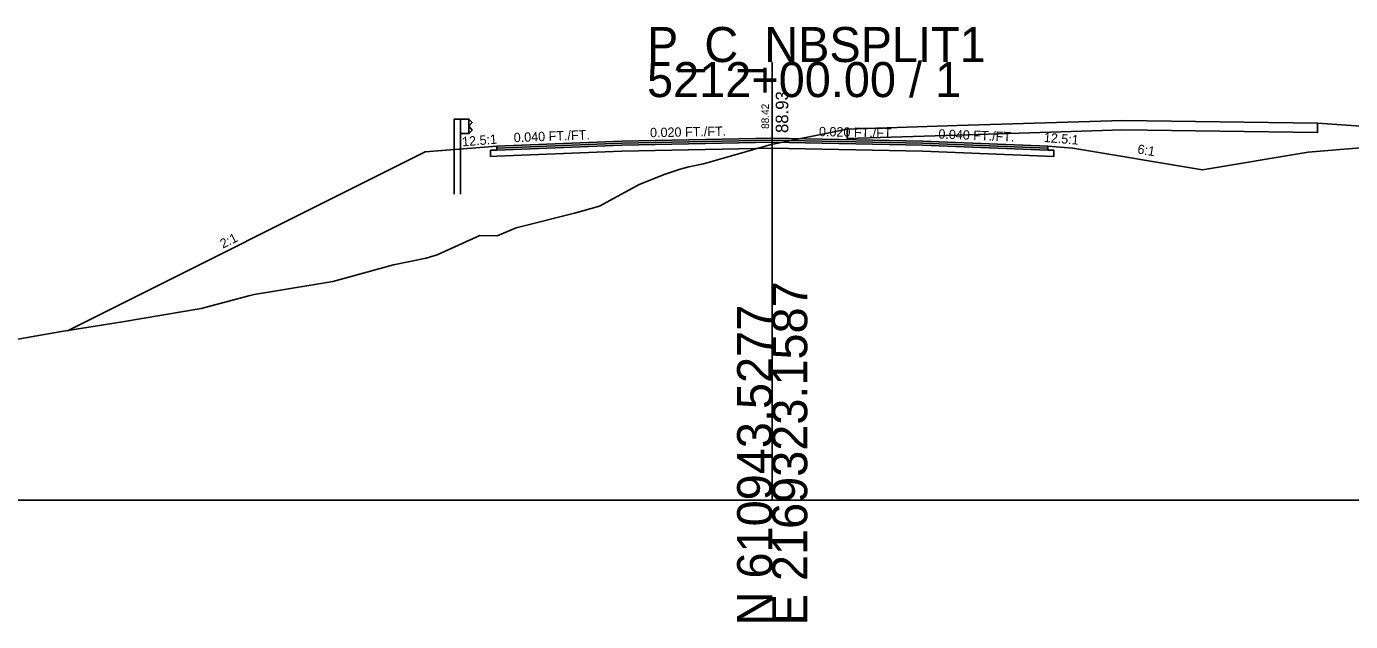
# Model space of a CAD drawing. Extents: x -26 to 1303, y -3010 to 12038.
# Drawn here: x 1090.4 to 1196.2, y 6990.3 to 7037.8 of the extents above; entities that cross this region are included whole.
import ezdxf

# ---------------------------------------------------------------- set-up
doc = ezdxf.new("R2010")
doc.units = 0
for name, color, linetype in [('RD_GPK_XS_Cell', 7, 'Continuous'), ('RD_PD_Final_TrvlWay', 7, 'Continuous'), ('RD_XS_Base', 7, 'Continuous'), ('RD_XS_ExGround', 7, 'Continuous'), ('RD_XS_ExPaveRet', 7, 'Continuous'), ('RD_XS_GR', 7, 'Continuous'), ('RD_XS_Greenside', 7, 'Continuous'), ('RD_XS_Pave', 7, 'Continuous'), ('RD_XS_PaveOvlay_CP', 7, 'Continuous'), ('RD_XS_TieSlope', 7, 'Continuous'), ('RD_XS_TX_Elev_EX', 7, 'Continuous'), ('RD_XS_TX_Elev_PR', 7, 'Continuous'), ('RD_XS_TX_ShdSlope', 7, 'Continuous'), ('RD_XS_TX_Slope', 7, 'Continuous')]:
    doc.layers.add(name, color=color, linetype=linetype)

msp = doc.modelspace()

# ---------------------------------------------------------------- linework, layer by layer
at = {"layer": 'RD_GPK_XS_Cell'}
for p, q in [((1150, 7000), (1150, 7035)), ((1000, 7000), (1150, 7000)), ((1150, 7000), (1300, 7000))]:
    msp.add_line(p, q, dxfattribs=at)
at = {"layer": 'RD_PD_Final_TrvlWay'}
for p, q in [((1125.11, 7028.05), (1124.61, 7028.01)), ((1124.61, 7028.01), (1124.61, 7024.45)), ((1125.11, 7024.45), (1125.11, 7028.05))]:
    msp.add_line(p, q, dxfattribs=at)
at = {"layer": 'RD_XS_Base'}
for p, q in [((1128, 7027.97), (1138, 7028.37)), ((1138, 7028.37), (1150, 7028.61)), ((1138, 7028.37), (1138, 7028.37)), ((1150, 7028.61), (1150, 7028.77)), ((1150, 7028.77), (1150, 7028.11)), ((1150, 7028.61), (1150, 7028.11)), ((1162, 7028.37), (1150, 7028.61)), ((1150, 7028.61), (1150, 7028.61)), ((1172, 7027.97), (1162, 7028.37)), ((1164, 7028.29), (1164, 7028.29)), ((1127.5, 7027.95), (1128, 7027.97)), ((1127.5, 7027.45), (1127.5, 7027.95)), ((1127.5, 7027.95), (1127.5, 7027.95)), ((1128, 7027.47), (1127.5, 7027.45)), ((1127.5, 7027.45), (1127.5, 7027.45)), ((1127.5, 7027.45), (1127.5, 7027.45)), ((1128, 7027.97), (1128, 7027.97)), ((1138, 7027.87), (1128, 7027.47)), ((1128, 7027.47), (1128, 7027.47)), ((1150, 7028.11), (1138, 7027.87)), ((1138, 7027.87), (1138, 7027.87)), ((1150, 7028.11), (1150, 7028.11)), ((1150, 7028.11), (1150, 7028.11)), ((1150, 7028.11), (1162, 7027.87)), ((1162, 7027.87), (1172.5, 7027.45)), ((1164, 7027.79), (1164, 7027.79)), ((1172.5, 7027.95), (1172, 7027.97)), ((1172, 7027.97), (1172, 7027.97)), ((1172.5, 7027.45), (1172.5, 7027.95)), ((1172.5, 7027.95), (1172.5, 7027.95)), ((1172.5, 7027.45), (1172.5, 7027.45)), ((1172.5, 7027.45), (1172.5, 7027.45))]:
    msp.add_line(p, q, dxfattribs=at)
at = {"layer": 'RD_XS_ExGround'}
msp.add_lwpolyline([(1081.56, 7011.43), (1093.24, 7013.47), (1098.1, 7014.26), (1104.38, 7015.3), (1108.21, 7016.32), (1108.63, 7016.44), (1109.78, 7016.63), (1114.9, 7017.46), (1119.75, 7018.81), (1122.36, 7019.33), (1122.98, 7019.51), (1123.25, 7019.59), (1126.64, 7021.14), (1128.03, 7021.12), (1129.56, 7021.75), (1134.2, 7022.94), (1136.21, 7023.5), (1139.38, 7025.22), (1141.45, 7026.04), (1142.64, 7026.45), (1143.34, 7026.64), (1144.5, 7026.87), (1149.91, 7028.41), (1155.99, 7029.64), (1164.76, 7029.92), (1178, 7030.34), (1185.74, 7030.23), (1193.56, 7030.11), (1201.68, 7029.57)], dxfattribs=at)
at = {"layer": 'RD_XS_ExPaveRet'}
msp.add_line((1164.76, 7029.92), (1155.99, 7029.64), dxfattribs=at)
for points in [[(1193.56, 7030.11), (1193.56, 7030.11), (1193.56, 7029.36), (1193.56, 7029.36), (1193.56, 7029.36), (1185.74, 7029.48), (1185.74, 7029.48), (1178, 7029.59), (1164.76, 7029.17), (1164.76, 7029.17), (1155.99, 7028.89), (1155.99, 7028.89), (1155.99, 7029.64), (1155.99, 7029.64), (1155.99, 7029.64), (1164.76, 7029.92), (1164.76, 7029.92), (1178, 7030.34), (1185.74, 7030.23), (1185.74, 7030.23), (1193.56, 7030.11), (1193.56, 7030.11), (1193.56, 7030.11)], [(1155.99, 7029.64), (1155.99, 7028.89), (1164.76, 7029.17), (1178, 7029.59), (1185.74, 7029.48), (1193.56, 7029.36), (1193.56, 7029.36), (1193.56, 7030.11), (1193.56, 7030.11), (1185.74, 7030.23), (1178, 7030.34), (1164.76, 7029.92)]]:
    msp.add_lwpolyline(points, dxfattribs=at)
at = {"layer": 'RD_XS_GR'}
for points in [[(1125.11, 7030.45), (1125.11, 7028.05), (1124.61, 7028.01), (1124.61, 7030.45), (1124.86, 7030.45), (1125.11, 7030.45)], [(1125.77, 7030.45), (1125.77, 7029.28), (1125.11, 7029.28), (1125.11, 7030.45), (1125.77, 7030.45)], [(1126.04, 7030.16), (1125.77, 7030.45), (1125.77, 7029.28), (1125.77, 7029.28), (1125.77, 7029.28), (1126.04, 7029.57), (1126.04, 7029.57), (1125.77, 7029.87), (1125.77, 7029.87), (1126.04, 7030.16), (1126.04, 7030.16)]]:
    msp.add_lwpolyline(points, dxfattribs=at)
at = {"layer": 'RD_XS_Greenside'}
for p, q in [((1122.29, 7027.83), (1093.72, 7013.54)), ((1174, 7028.13), (1184.36, 7026.4)), ((1192.81, 7027.81), (1184.36, 7026.4))]:
    msp.add_line(p, q, dxfattribs=at)
at = {"layer": 'RD_XS_Pave'}
for p, q in [((1138, 7028.69), (1128, 7028.29)), ((1138, 7028.53), (1128, 7028.13)), ((1128, 7028.13), (1138, 7028.53)), ((1128, 7027.97), (1138, 7028.37)), ((1128, 7028.29), (1128, 7028.29)), ((1128, 7028.29), (1128, 7028.13)), ((1150, 7028.93), (1138, 7028.69)), ((1150, 7028.77), (1138, 7028.53)), ((1138, 7028.53), (1150, 7028.77)), ((1138, 7028.69), (1138, 7028.69)), ((1138, 7028.37), (1150, 7028.61)), ((1138, 7028.53), (1138, 7028.53)), ((1138, 7028.53), (1138, 7028.53)), ((1138, 7028.37), (1138, 7028.37)), ((1162, 7028.69), (1150, 7028.93)), ((1150, 7028.61), (1150, 7028.77)), ((1150, 7028.77), (1162, 7028.53)), ((1162, 7028.53), (1150, 7028.77)), ((1150, 7028.77), (1150, 7028.61)), ((1150, 7028.61), (1150, 7028.61)), ((1150, 7028.61), (1150, 7028.61)), ((1150, 7028.61), (1162, 7028.37)), ((1172, 7028.29), (1162, 7028.69)), ((1162, 7028.53), (1172, 7028.13)), ((1172, 7028.13), (1162, 7028.53)), ((1162, 7028.37), (1172, 7027.97)), ((1164, 7028.61), (1164, 7028.61)), ((1164, 7028.45), (1164, 7028.45)), ((1164, 7028.45), (1164, 7028.45)), ((1164, 7028.29), (1164, 7028.29)), ((1172, 7028.13), (1172, 7028.29)), ((1172, 7028.29), (1172, 7028.29)), ((1128, 7028.13), (1128, 7028.13)), ((1128, 7028.13), (1128, 7027.97)), ((1128, 7028.13), (1128, 7028.13)), ((1128, 7028.13), (1128, 7028.13)), ((1128, 7027.97), (1128, 7027.97)), ((1128, 7027.97), (1128, 7027.97)), ((1172, 7028.13), (1172, 7028.13)), ((1172, 7028.13), (1172, 7028.13)), ((1172, 7027.97), (1172, 7028.13)), ((1172, 7028.13), (1172, 7028.13)), ((1172, 7027.97), (1172, 7027.97)), ((1172, 7027.97), (1172, 7027.97))]:
    msp.add_line(p, q, dxfattribs=at)
at = {"layer": 'RD_XS_PaveOvlay_CP'}
for p, q in [((1128, 7028.29), (1138, 7028.69)), ((1138, 7028.69), (1150, 7028.93)), ((1150, 7028.93), (1162, 7028.69)), ((1162, 7028.69), (1172, 7028.29))]:
    msp.add_line(p, q, dxfattribs=at)
at = {"layer": 'RD_XS_TieSlope'}
for p, q in [((1128, 7028.29), (1122.29, 7027.83)), ((1172, 7028.29), (1174, 7028.13)), ((1198.81, 7028.29), (1192.81, 7027.81))]:
    msp.add_line(p, q, dxfattribs=at)

# ---------------------------------------------------------------- texts
at = {"layer": 'RD_GPK_XS_Cell'}
for s, p in [('P_C_NBSPLIT1', (1140, 7035)), ('5212+00.00 / 1', (1140, 7032.2))]:
    msp.add_text(s, height=2.8, dxfattribs=at).set_placement(p)
for s, p in [('E 2169323.1587', (1152.8, 6990)), ('N 610943.5277', (1150, 6990))]:
    msp.add_text(s, height=2.8, rotation=90, dxfattribs=at).set_placement(p)
at = {"layer": 'RD_XS_TX_Elev_EX'}
msp.add_text('88.42', height=0.6, rotation=90, dxfattribs=at).set_placement((1149.74, 7029.66))
at = {"layer": 'RD_XS_TX_Elev_PR'}
msp.add_text('88.93', height=1, rotation=90, dxfattribs=at).set_placement((1151.28, 7029.33))
at = {"layer": 'RD_XS_TX_ShdSlope'}
for rotation, p in [(355.4261, (1171.67, 7028.62)), (4.5739, (1125.26, 7028.26))]:
    msp.add_text('12.5:1', height=0.75, rotation=rotation, dxfattribs=at).set_placement(p)
at = {"layer": 'RD_XS_TX_Slope'}
for s, rotation, p in [('0.040 FT./FT.', 2.2906, (1129.37, 7028.59)), ('0.020 FT./FT.', 1.1458, (1140.25, 7028.99)), ('0.020 FT./FT.', 358.8542, (1153.73, 7029.08)), ('0.040 FT./FT.', 357.7094, (1163.26, 7028.89)), ('6:1', 350.5377, (1179.13, 7027.7)), ('2:1', 26.5651, (1106.13, 7020.09))]:
    msp.add_text(s, height=0.75, rotation=rotation, dxfattribs=at).set_placement(p)

doc.saveas('drawing.dxf')
